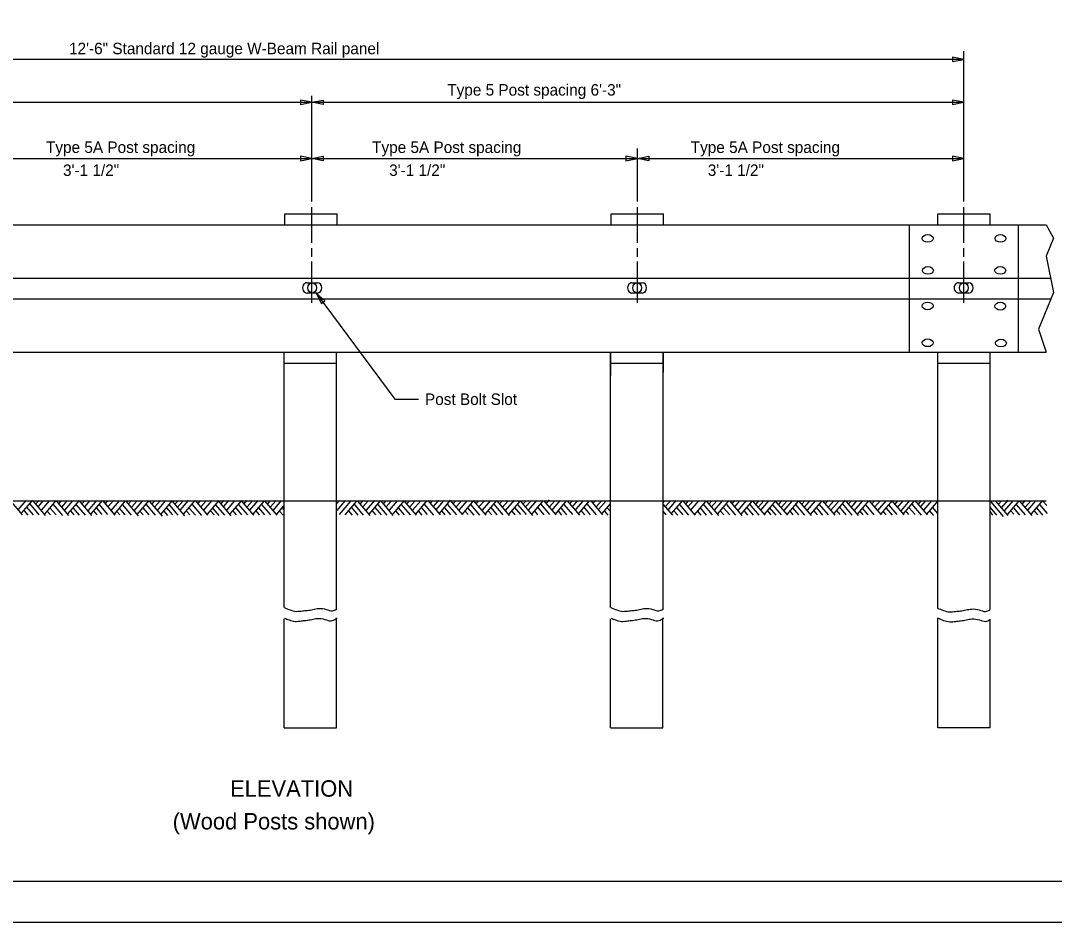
# Model space of a CAD drawing. Extents: x -0.7 to 88.8, y -25.9 to 22.
# Drawn here: x 9.82 to 22.43, y 0 to 11 of the extents above; entities that cross this region are included whole.
import ezdxf

# ---------------------------------------------------------------- set-up
doc = ezdxf.new("R2010")
doc.units = 0
for name, color, linetype in [('Default', 7, 'Continuous'), ('SH_Border', 7, 'Continuous'), ('ST_Text', 7, 'Continuous')]:
    doc.layers.add(name, color=color, linetype=linetype)

msp = doc.modelspace()

# ---------------------------------------------------------------- linework, layer by layer
at = {"layer": 'Default'}
for p, q in [((21.331, 8.796), (21.331, 10.628)), ((21.331, 10.528), (5.395, 10.528)), ((5.395, 10.004), (13.375, 10.004)), ((13.375, 8.796), (13.375, 10.082)), ((13.375, 10.004), (21.331, 10.004)), ((17.347, 8.796), (17.347, 9.442)), ((9.381, 9.319), (13.375, 9.319)), ((13.375, 9.319), (17.347, 9.319)), ((17.347, 9.319), (21.331, 9.319)), ((13.375, 8.289), (13.375, 8.724)), ((17.347, 8.289), (17.347, 8.724)), ((21.331, 8.289), (21.331, 8.724)), ((13.045, 8.644), (13.683, 8.644)), ((13.045, 8.508), (13.045, 8.643)), ((13.683, 8.508), (13.683, 8.643)), ((17.029, 8.644), (17.667, 8.644)), ((17.029, 8.508), (17.029, 8.644)), ((17.667, 8.508), (17.667, 8.644)), ((21.014, 8.644), (21.651, 8.644)), ((21.014, 8.508), (21.014, 8.644)), ((21.651, 8.508), (21.651, 8.644)), ((3.85, 8.508), (22.336, 8.508)), ((20.667, 6.956), (20.667, 8.508)), ((21.999, 6.956), (21.999, 8.508)), ((22.336, 8.508), (22.424, 8.346)), ((22.424, 8.346), (22.333, 8.129)), ((13.375, 8.117), (13.375, 8.226)), ((17.347, 8.117), (17.347, 8.226)), ((21.331, 8.117), (21.331, 8.226)), ((22.333, 8.129), (22.424, 7.683)), ((13.375, 7.556), (13.375, 8.06)), ((17.347, 7.556), (17.347, 8.06)), ((21.331, 7.556), (21.331, 8.06)), ((4.063, 7.859), (22.396, 7.859)), ((13.316, 7.802), (13.379, 7.802)), ((13.379, 7.802), (13.443, 7.802)), ((17.28, 7.802), (17.343, 7.802)), ((17.343, 7.802), (17.407, 7.802)), ((21.265, 7.802), (21.329, 7.802)), ((21.329, 7.802), (21.392, 7.802)), ((4.031, 7.608), (22.393, 7.608)), ((13.379, 7.677), (13.316, 7.677)), ((13.443, 7.677), (13.379, 7.677)), ((17.343, 7.677), (17.28, 7.677)), ((17.407, 7.677), (17.343, 7.677)), ((21.329, 7.677), (21.265, 7.677)), ((21.392, 7.677), (21.329, 7.677)), ((22.424, 7.683), (22.241, 7.237)), ((22.241, 7.237), (22.336, 6.956)), ((3.85, 6.956), (22.336, 6.956)), ((13.036, 3.84), (13.036, 6.956)), ((13.677, 3.817), (13.677, 6.956)), ((17.02, 5.141), (17.02, 6.956)), ((17.02, 6.956), (17.02, 6.673)), ((17.661, 3.817), (17.661, 6.956)), ((17.661, 6.956), (17.661, 6.71)), ((21.014, 3.833), (21.014, 6.957)), ((21.651, 3.816), (21.651, 6.956)), ((13.036, 6.823), (13.677, 6.823)), ((17.02, 6.823), (17.661, 6.823)), ((21.014, 6.823), (21.651, 6.823)), ((3.85, 5.143), (22.336, 5.143)), ((9.843, 4.972), (9.692, 5.149)), ((9.694, 5.143), (13.036, 5.143)), ((9.792, 5.031), (9.889, 5.145)), ((9.83, 4.987), (9.97, 5.152)), ((9.977, 4.972), (9.898, 5.065)), ((10.048, 4.972), (9.932, 5.109)), ((10.126, 4.965), (9.976, 5.142)), ((10.007, 5.104), (10.042, 5.145)), ((10.038, 5.075), (10.096, 5.143)), ((10.079, 5.031), (10.174, 5.143)), ((10.116, 4.98), (10.256, 5.145)), ((10.255, 4.97), (10.184, 5.054)), ((10.335, 4.964), (10.221, 5.098)), ((10.409, 4.965), (10.259, 5.142)), ((10.293, 5.111), (10.317, 5.139)), ((10.324, 5.064), (10.393, 5.145)), ((10.362, 5.027), (10.46, 5.143)), ((10.399, 4.983), (10.538, 5.146)), ((10.54, 4.968), (10.467, 5.054)), ((10.612, 4.968), (10.504, 5.094)), ((10.689, 4.965), (10.539, 5.142)), ((10.573, 5.108), (10.603, 5.143)), ((10.611, 5.075), (10.668, 5.143)), ((10.648, 5.023), (10.751, 5.145)), ((10.682, 4.983), (10.821, 5.146)), ((10.818, 4.974), (10.75, 5.054)), ((10.885, 4.975), (10.778, 5.101)), ((10.975, 4.969), (10.825, 5.145)), ((10.859, 5.111), (10.886, 5.143)), ((10.891, 5.071), (10.953, 5.145)), ((10.928, 5.024), (11.028, 5.141)), ((10.965, 4.98), (11.102, 5.141)), ((11.098, 4.97), (11.027, 5.054)), ((11.175, 4.968), (11.067, 5.094)), ((11.258, 4.961), (11.108, 5.138)), ((11.139, 5.104), (11.174, 5.145)), ((11.177, 5.067), (11.238, 5.139)), ((11.205, 5.02), (11.303, 5.136)), ((11.245, 4.976), (11.389, 5.145)), ((11.389, 4.972), (11.316, 5.057)), ((11.467, 4.968), (11.357, 5.098)), ((11.551, 4.957), (11.4, 5.134)), ((11.429, 5.108), (11.459, 5.143)), ((11.46, 5.067), (11.524, 5.143)), ((11.491, 5.024), (11.595, 5.147)), ((11.531, 4.976), (11.675, 5.145)), ((11.679, 4.972), (11.606, 5.057)), ((11.745, 4.966), (11.637, 5.094)), ((11.824, 4.961), (11.674, 5.138)), ((11.709, 5.104), (11.742, 5.143)), ((11.737, 5.064), (11.804, 5.143)), ((11.774, 5.031), (11.871, 5.145)), ((11.808, 4.98), (11.95, 5.147)), ((11.954, 4.966), (11.879, 5.054)), ((12.033, 4.964), (11.92, 5.098)), ((12.107, 4.968), (11.957, 5.145)), ((11.989, 5.108), (12.018, 5.143)), ((12.023, 5.071), (12.084, 5.143)), ((12.057, 5.027), (12.157, 5.145)), ((12.101, 4.98), (12.244, 5.148)), ((12.243, 4.963), (12.169, 5.05)), ((12.312, 4.966), (12.203, 5.094)), ((12.39, 4.961), (12.24, 5.138)), ((12.269, 5.104), (12.303, 5.145)), ((12.3, 5.071), (12.364, 5.147)), ((12.34, 5.031), (12.435, 5.143)), ((12.38, 4.983), (12.519, 5.147)), ((12.522, 4.97), (12.446, 5.059)), ((12.592, 4.971), (12.482, 5.1)), ((12.669, 4.967), (12.518, 5.143)), ((12.548, 5.107), (12.583, 5.148)), ((12.585, 5.068), (12.649, 5.143)), ((12.619, 5.028), (12.718, 5.145)), ((12.659, 4.98), (12.797, 5.143)), ((12.803, 4.971), (12.729, 5.057)), ((12.874, 4.97), (12.764, 5.098)), ((12.953, 4.967), (12.803, 5.143)), ((12.836, 5.107), (12.867, 5.144)), ((12.871, 5.068), (12.935, 5.143)), ((12.905, 5.027), (13.006, 5.146)), ((12.948, 4.98), (13.033, 5.08)), ((13.035, 5.036), (13.017, 5.057)), ((13.677, 5.104), (13.712, 5.145)), ((13.677, 5.143), (17.02, 5.143)), ((13.682, 5.023), (13.787, 5.147)), ((13.714, 4.976), (13.852, 5.139)), ((13.781, 4.972), (13.919, 5.135)), ((13.939, 4.969), (13.861, 5.061)), ((14.006, 4.969), (13.895, 5.1)), ((14.088, 4.963), (13.938, 5.14)), ((13.969, 5.107), (14.002, 5.146)), ((13.998, 5.068), (14.061, 5.142)), ((14.041, 5.027), (14.142, 5.145)), ((14.076, 4.981), (14.215, 5.145)), ((14.223, 4.97), (14.147, 5.059)), ((14.295, 4.968), (14.182, 5.1)), ((14.369, 4.965), (14.219, 5.142)), ((14.252, 5.109), (14.28, 5.142)), ((14.282, 5.068), (14.342, 5.139)), ((14.321, 5.027), (14.418, 5.141)), ((14.367, 4.984), (14.505, 5.147)), ((14.504, 4.972), (14.434, 5.055)), ((14.578, 4.972), (14.47, 5.098)), ((14.653, 4.967), (14.503, 5.144)), ((14.536, 5.109), (14.565, 5.143)), ((14.57, 5.068), (14.631, 5.139)), ((14.605, 5.027), (14.703, 5.143)), ((14.644, 4.981), (14.783, 5.145)), ((14.786, 4.974), (14.715, 5.057)), ((14.863, 4.967), (14.746, 5.106)), ((14.943, 4.97), (14.793, 5.147)), ((14.822, 5.111), (14.849, 5.143)), ((14.865, 5.078), (14.926, 5.15)), ((14.893, 5.032), (14.985, 5.141)), ((14.932, 4.989), (15.068, 5.149)), ((15.071, 4.97), (14.997, 5.057)), ((15.144, 4.971), (15.032, 5.103)), ((15.219, 4.97), (15.068, 5.147)), ((15.105, 5.111), (15.132, 5.143)), ((15.14, 5.071), (15.201, 5.142)), ((15.173, 5.027), (15.27, 5.142)), ((15.212, 4.981), (15.35, 5.145)), ((15.354, 4.969), (15.279, 5.057)), ((15.426, 4.966), (15.313, 5.098)), ((15.502, 4.967), (15.352, 5.144)), ((15.383, 5.111), (15.409, 5.143)), ((15.417, 5.071), (15.48, 5.144)), ((15.459, 5.027), (15.559, 5.146)), ((15.495, 4.984), (15.634, 5.147)), ((15.637, 4.972), (15.562, 5.06)), ((15.708, 4.972), (15.599, 5.101)), ((15.786, 4.965), (15.636, 5.142)), ((15.667, 5.109), (15.7, 5.148)), ((15.703, 5.066), (15.77, 5.144)), ((15.738, 5.025), (15.846, 5.152)), ((15.777, 4.976), (15.916, 5.14)), ((15.925, 4.975), (15.853, 5.06)), ((15.993, 4.974), (15.887, 5.098)), ((16.072, 4.965), (15.922, 5.142)), ((15.959, 5.109), (15.988, 5.143)), ((15.987, 5.071), (16.05, 5.144)), ((16.02, 5.027), (16.12, 5.145)), ((16.063, 4.984), (16.202, 5.147)), ((16.211, 4.971), (16.132, 5.064)), ((16.277, 4.975), (16.167, 5.105)), ((16.355, 4.97), (16.204, 5.147)), ((16.235, 5.106), (16.276, 5.154)), ((16.275, 5.067), (16.337, 5.14)), ((16.306, 5.029), (16.404, 5.145)), ((16.346, 4.979), (16.484, 5.142)), ((16.487, 4.973), (16.415, 5.058)), ((16.561, 4.975), (16.455, 5.099)), ((16.643, 4.967), (16.493, 5.144)), ((16.524, 5.109), (16.554, 5.144)), ((16.556, 5.07), (16.616, 5.141)), ((16.597, 5.035), (16.686, 5.14)), ((16.627, 4.985), (16.762, 5.144)), ((16.775, 4.971), (16.694, 5.067)), ((16.849, 4.97), (16.734, 5.105)), ((16.927, 4.973), (16.782, 5.144)), ((16.805, 5.109), (16.836, 5.145)), ((16.848, 5.073), (16.908, 5.144)), ((16.873, 5.035), (16.965, 5.144)), ((16.918, 4.988), (17.019, 5.107)), ((17.02, 5.011), (16.98, 5.058)), ((17.02, 3.84), (17.02, 5.141)), ((17.66, 5.119), (17.679, 5.142)), ((17.661, 5.143), (21.014, 5.143)), ((17.778, 4.967), (17.662, 5.103)), ((17.691, 5.073), (17.75, 5.143)), ((17.721, 5.029), (17.82, 5.145)), ((17.761, 4.985), (17.9, 5.148)), ((17.906, 4.97), (17.828, 5.061)), ((17.976, 4.967), (17.864, 5.099)), ((18.054, 4.967), (17.904, 5.144)), ((17.937, 5.103), (17.972, 5.144)), ((17.962, 5.067), (18.027, 5.143)), ((17.997, 5.023), (18.098, 5.142)), ((18.043, 4.973), (18.181, 5.136)), ((18.191, 4.968), (18.117, 5.055)), ((18.265, 4.97), (18.152, 5.102)), ((18.34, 4.964), (18.19, 5.141)), ((18.221, 5.106), (18.254, 5.144)), ((18.251, 5.067), (18.315, 5.143)), ((18.289, 5.029), (18.389, 5.147)), ((18.324, 4.979), (18.463, 5.142)), ((18.473, 4.97), (18.398, 5.058)), ((18.549, 4.969), (18.438, 5.099)), ((18.626, 4.964), (18.476, 5.141)), ((18.502, 5.106), (18.537, 5.147)), ((18.537, 5.07), (18.599, 5.143)), ((18.575, 5.026), (18.675, 5.144)), ((18.612, 4.979), (18.751, 5.142)), ((18.765, 4.968), (18.684, 5.064)), ((18.834, 4.968), (18.719, 5.102)), ((18.905, 4.967), (18.754, 5.143)), ((18.797, 5.102), (18.83, 5.142)), ((18.826, 5.068), (18.888, 5.141)), ((18.855, 5.03), (18.951, 5.143)), ((18.896, 4.979), (19.035, 5.142)), ((19.039, 4.969), (18.961, 5.061)), ((19.104, 4.971), (18.999, 5.095)), ((19.181, 4.966), (19.037, 5.136)), ((19.071, 5.099), (19.11, 5.145)), ((19.106, 5.065), (19.17, 5.14)), ((19.138, 5.023), (19.237, 5.14)), ((19.173, 4.975), (19.312, 5.139)), ((19.318, 4.97), (19.244, 5.057)), ((19.391, 4.969), (19.282, 5.098)), ((19.47, 4.963), (19.32, 5.139)), ((19.354, 5.102), (19.389, 5.144)), ((19.386, 5.065), (19.455, 5.145)), ((19.424, 5.03), (19.52, 5.144)), ((19.459, 4.975), (19.598, 5.139)), ((19.61, 4.969), (19.536, 5.057)), ((19.68, 4.97), (19.571, 5.098)), ((19.759, 4.966), (19.608, 5.143)), ((19.646, 5.113), (19.676, 5.148)), ((19.678, 5.068), (19.739, 5.14)), ((19.707, 5.027), (19.8, 5.136)), ((19.748, 4.986), (19.887, 5.149)), ((19.893, 4.973), (19.816, 5.064)), ((19.969, 4.969), (19.854, 5.105)), ((20.045, 4.963), (19.894, 5.139)), ((19.929, 5.109), (19.958, 5.143)), ((19.961, 5.065), (20.026, 5.141)), ((19.996, 5.023), (20.095, 5.14)), ((20.031, 4.979), (20.17, 5.142)), ((20.163, 4.971), (20.093, 5.054)), ((20.237, 4.973), (20.137, 5.091)), ((20.325, 4.97), (20.174, 5.146)), ((20.209, 5.106), (20.241, 5.143)), ((20.241, 5.065), (20.308, 5.143)), ((20.282, 5.023), (20.382, 5.141)), ((20.32, 4.982), (20.458, 5.145)), ((20.458, 4.968), (20.385, 5.054)), ((20.516, 4.975), (20.414, 5.095)), ((20.602, 4.97), (20.452, 5.146)), ((20.492, 5.102), (20.526, 5.143)), ((20.521, 5.061), (20.589, 5.141)), ((20.568, 5.023), (20.671, 5.145)), ((20.588, 4.979), (20.727, 5.142)), ((20.735, 4.975), (20.665, 5.057)), ((20.814, 4.968), (20.7, 5.102)), ((20.888, 4.97), (20.738, 5.146)), ((20.775, 5.102), (20.812, 5.147)), ((20.804, 5.071), (20.862, 5.14)), ((20.842, 5.027), (20.939, 5.141)), ((20.88, 4.979), (21.019, 5.142)), ((21.013, 4.987), (20.948, 5.064)), ((21.651, 5.143), (22.336, 5.143)), ((21.734, 4.966), (21.654, 5.061)), ((21.813, 4.952), (21.663, 5.129)), ((21.871, 4.963), (21.721, 5.139)), ((21.758, 5.106), (21.79, 5.143)), ((21.793, 5.061), (21.87, 5.152)), ((21.828, 5.02), (21.933, 5.143)), ((21.866, 4.979), (22.005, 5.142)), ((22.014, 4.969), (21.943, 5.054)), ((22.081, 4.97), (21.972, 5.098)), ((22.163, 4.963), (22.013, 5.14)), ((22.044, 5.106), (22.079, 5.147)), ((22.079, 5.065), (22.146, 5.143)), ((22.111, 5.027), (22.21, 5.143)), ((22.155, 4.982), (22.294, 5.146)), ((22.294, 4.969), (22.22, 5.057)), ((22.351, 4.988), (22.258, 5.098)), ((22.342, 5.085), (22.299, 5.136)), ((9.912, 4.968), (9.867, 5.021)), ((10.187, 4.97), (10.147, 5.017)), ((10.473, 4.973), (10.433, 5.021)), ((10.756, 4.97), (10.713, 5.021)), ((11.031, 4.972), (10.996, 5.013)), ((11.318, 4.972), (11.282, 5.013)), ((11.616, 4.964), (11.571, 5.017)), ((11.885, 4.97), (11.848, 5.013)), ((12.182, 4.972), (12.144, 5.017)), ((12.454, 4.973), (12.414, 5.019)), ((12.737, 4.971), (12.696, 5.019)), ((13.023, 4.969), (12.982, 5.018)), ((13.871, 4.968), (13.827, 5.019)), ((14.156, 4.971), (14.113, 5.021)), ((14.444, 4.969), (14.401, 5.019)), ((14.719, 4.969), (14.676, 5.019)), ((15.003, 4.971), (14.964, 5.017)), ((15.281, 4.975), (15.246, 5.017)), ((15.571, 4.971), (15.528, 5.022)), ((15.856, 4.971), (15.818, 5.017)), ((16.134, 4.972), (16.094, 5.02)), ((16.426, 4.968), (16.383, 5.02)), ((16.707, 4.972), (16.664, 5.022)), ((16.992, 4.967), (16.95, 5.017)), ((17.7, 4.97), (17.661, 5.015)), ((17.839, 4.969), (17.793, 5.022)), ((18.125, 4.969), (18.082, 5.019)), ((18.402, 4.97), (18.363, 5.016)), ((18.695, 4.968), (18.652, 5.019)), ((18.979, 4.97), (18.935, 5.023)), ((19.249, 4.972), (19.206, 5.023)), ((19.543, 4.973), (19.503, 5.019)), ((19.82, 4.976), (19.781, 5.023)), ((20.102, 4.971), (20.064, 5.016)), ((20.383, 4.973), (20.347, 5.016)), ((20.659, 4.975), (20.618, 5.023)), ((20.965, 4.964), (20.913, 5.026)), ((21.686, 4.968), (21.654, 5.006)), ((21.94, 4.978), (21.905, 5.019)), ((22.232, 4.971), (22.191, 5.019)), ((13.036, 2.374), (13.036, 3.701)), ((13.669, 3.711), (13.683, 3.711)), ((13.674, 2.374), (13.674, 3.707)), ((17.02, 2.374), (17.02, 3.701)), ((17.653, 3.711), (17.668, 3.711)), ((17.658, 2.374), (17.658, 3.707)), ((21.011, 2.374), (21.011, 3.712)), ((21.651, 2.374), (21.651, 3.699)), ((13.036, 2.372), (13.674, 2.372)), ((17.02, 2.372), (17.658, 2.372)), ((21.014, 2.375), (21.651, 2.375))]:
    msp.add_line(p, q, dxfattribs=at)
for points in [[(21.191, 10.5), (21.331, 10.528), (21.191, 10.556)], [(13.235, 9.976), (13.375, 10.004), (13.235, 10.032)], [(13.515, 9.976), (13.375, 10.004), (13.515, 10.032)], [(21.191, 9.976), (21.331, 10.004), (21.191, 10.032)], [(13.235, 9.291), (13.375, 9.319), (13.235, 9.347)], [(13.515, 9.291), (13.375, 9.319), (13.515, 9.347)], [(17.207, 9.291), (17.347, 9.319), (17.207, 9.347)], [(17.487, 9.291), (17.347, 9.319), (17.487, 9.347)], [(21.191, 9.291), (21.331, 9.319), (21.191, 9.347)], [(13.535, 7.584), (13.426, 7.677), (13.491, 7.55)]]:
    msp.add_lwpolyline(points, close=True, dxfattribs=at)
msp.add_lwpolyline([(13.426, 7.677), (14.386, 6.384), (14.677, 6.384)], dxfattribs=at)
for centre, major_axis, ratio in [((20.889, 8.344), (-0.0664, 0), 0.705181), ((21.777, 8.344), (-0.0664, 0), 0.705181), ((20.892, 7.953), (-0.0664, 0), 0.705181), ((21.775, 7.953), (-0.0664, 0), 0.705181), ((13.379, 7.74), (0, 0.0625), 0.850089), ((17.343, 7.74), (0, 0.0625), 0.850089), ((21.329, 7.74), (0, 0.0625), 0.850089), ((20.889, 7.52), (-0.0664, 0), 0.705181), ((21.775, 7.517), (-0.0664, 0), 0.705181), ((20.889, 7.07), (-0.0664, 0), 0.705181), ((21.783, 7.067), (-0.0664, 0), 0.705181)]:
    msp.add_ellipse(centre, major_axis=major_axis, ratio=ratio, dxfattribs=at)
for centre, start_param, end_param in [((13.316, 7.74), 0, 3.141593), ((13.443, 7.74), 3.141593, 6.283185), ((17.28, 7.74), 0, 3.141593), ((17.407, 7.74), 3.141593, 6.283185), ((21.265, 7.74), 0, 3.141593), ((21.392, 7.74), 3.141593, 6.283185)]:
    msp.add_ellipse(centre, major_axis=(0, 0.0625), ratio=0.850089, start_param=start_param, end_param=end_param, dxfattribs=at)
for points in [[(13.039, 3.84), (13.112, 3.811), (13.186, 3.794), (13.26, 3.8), (13.319, 3.805), (13.388, 3.817), (13.457, 3.829), (13.551, 3.817), (13.625, 3.8), (13.676, 3.82)], [(17.023, 3.84), (17.097, 3.811), (17.171, 3.794), (17.244, 3.8), (17.304, 3.805), (17.373, 3.817), (17.442, 3.829), (17.535, 3.817), (17.609, 3.8), (17.66, 3.82)], [(21.007, 3.834), (21.081, 3.805), (21.155, 3.787), (21.229, 3.793), (21.288, 3.799), (21.357, 3.811), (21.426, 3.822), (21.519, 3.811), (21.593, 3.793), (21.652, 3.816)], [(13.042, 3.711), (13.097, 3.69), (13.171, 3.672), (13.245, 3.678), (13.304, 3.684), (13.373, 3.695), (13.442, 3.707), (13.535, 3.695), (13.609, 3.678), (13.669, 3.701)], [(17.026, 3.711), (17.081, 3.69), (17.155, 3.672), (17.229, 3.678), (17.288, 3.684), (17.357, 3.695), (17.426, 3.707), (17.52, 3.695), (17.594, 3.678), (17.653, 3.701)], [(21.01, 3.713), (21.084, 3.684), (21.158, 3.667), (21.231, 3.672), (21.291, 3.678), (21.36, 3.69), (21.429, 3.701), (21.522, 3.69), (21.596, 3.672), (21.65, 3.694)]]:
    msp.add_spline(points, degree=3, dxfattribs=at)
at = {"layer": 'SH_Border'}
msp.add_lwpolyline([(1.5, 21.5), (33.5, 21.5), (33.5, 0.5), (1.5, 0.5)], close=True, dxfattribs=at)
at = {"layer": 'ST_Text'}
msp.add_lwpolyline([(0, 0), (34, 0), (34, 22), (0, 22)], close=True, dxfattribs=at)

# ---------------------------------------------------------------- texts
at = {"layer": 'Default'}
for s, height, p in [('12\'-6" Standard 12 gauge W-Beam Rail panel', 0.14, (10.412, 10.591)), ('Type 5 Post spacing 6\'-3"', 0.14, (15.027, 10.086)), ('Type 5A Post spacing', 0.14, (10.131, 9.386)), ('Type 5A Post spacing', 0.14, (14.11, 9.386)), ('Type 5A Post spacing', 0.14, (17.998, 9.386)), ('    3\'-1 1/2"', 0.14, (10.131, 9.106)), ('    3\'-1 1/2"', 0.14, (14.11, 9.106)), ('    3\'-1 1/2" ', 0.14, (17.998, 9.106)), ('Post Bolt Slot', 0.14, (14.755, 6.312)), ('ELEVATION', 0.2, (12.377, 1.533)), ('(Wood Posts shown)', 0.2, (11.677, 1.133))]:
    msp.add_text(s, height=height, dxfattribs=at).set_placement(p)

doc.saveas('drawing.dxf')
